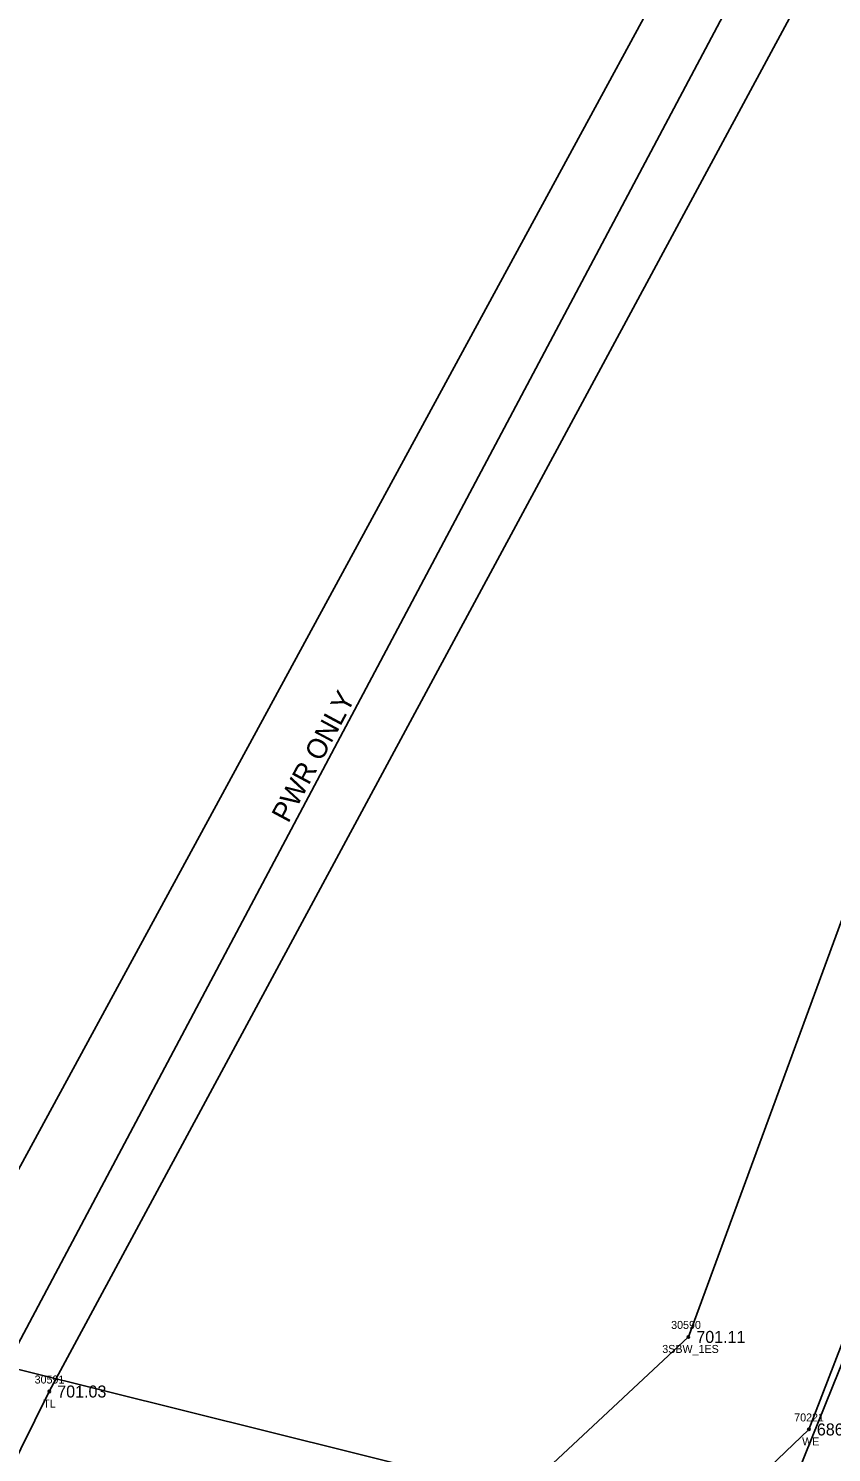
# Model space of a CAD drawing. Extents: x 1375131 to 1378678, y 999028 to 1004053.
# Drawn here: x 1377457.9 to 1377558.2, y 1001844.5 to 1002022.4 of the extents above; entities that cross this region are included whole.
import ezdxf

# ---------------------------------------------------------------- set-up
doc = ezdxf.new("R2010")
doc.units = 0
for name, color, linetype in [('RD_EX_DV_Prop', 7, 'Continuous'), ('RD_EX_Fence_Other', 7, 'Continuous'), ('RD_EX_Fence_Other_txCode', 7, 'Continuous'), ('RD_EX_H2O', 7, 'Continuous'), ('RD_EX_H2O_txCode', 7, 'Continuous'), ('RD_EX_SU_Elec', 7, 'Continuous'), ('RD_EX_TX_Fence_Other_ELEV', 7, 'Continuous'), ('RD_EX_TX_H2O_ELEV', 7, 'Continuous'), ('RD_EX_TX_VEG_ELEV', 7, 'Continuous'), ('RD_EX_VEG', 7, 'Continuous'), ('RD_EX_VEG_txCode', 7, 'Continuous'), ('RD_SMD_Locator', 7, 'Continuous'), ('RD_TX_Utilities', 7, 'Continuous')]:
    doc.layers.add(name, color=color, linetype=linetype)

msp = doc.modelspace()

# ---------------------------------------------------------------- linework, layer by layer
at = {"layer": 'RD_EX_DV_Prop'}
for points in [[(1377549.86, 1001831.61), (1377611.45, 1001984.12), (1377670.59, 1002066), (1377702.9, 1002207.93), (1377884.59, 1002382.26), (1377952.03, 1002369.22), (1378007.15, 1002415.65), (1377966.32, 1002503.97)], [(1377239.22, 1001933.68), (1377316.8, 1001925.5), (1377415.78, 1001865), (1377549.86, 1001831.61)]]:
    msp.add_lwpolyline(points, dxfattribs=at)
at = {"layer": 'RD_EX_Fence_Other'}
msp.add_lwpolyline([(1377637.49, 1002082.79), (1377602.37, 1002057.58), (1377580.56, 1002027.27), (1377564.26, 1001923.93), (1377540.33, 1001858.9), (1377456.19, 1001780.35), (1377421.26, 1001757.98), (1377378.17, 1001733.06)], dxfattribs=at)
at = {"layer": 'RD_EX_H2O'}
msp.add_lwpolyline([(1377375.48, 1001712.38), (1377425.1, 1001742.05), (1377478.82, 1001780.63), (1377516.49, 1001810.1), (1377555.39, 1001847.34), (1377570.71, 1001887.01), (1377585.15, 1001942.13), (1377603.16, 1001999.03), (1377641.82, 1002043.69), (1377653.81, 1002063.49)], dxfattribs=at)
at = {"layer": 'RD_EX_SU_Elec'}
msp.add_lwpolyline([(1377174.65, 1001934.87), (1377247.04, 1001903.65), (1377437.44, 1001822.1), (1377567.31, 1002066.68)], dxfattribs=at)
at = {"layer": 'RD_EX_VEG'}
for points in [[(1377636.58, 1002090.08), (1377595.82, 1002067.58), (1377573.9, 1002031.25), (1377561.3, 1002039.21), (1377460.46, 1001852.08), (1377433.84, 1001798.31), (1377321.3, 1001854.67)], [(1377534.01, 1002073.13), (1377547.87, 1002047.96), (1377449.99, 1001867.71), (1377414.83, 1001847.8), (1377322.94, 1001881.51), (1377257.82, 1001917.47), (1377246.23, 1001920.57)]]:
    msp.add_lwpolyline(points, dxfattribs=at)
at = {"layer": 'RD_SMD_Locator'}
for centre in [(1377540.33, 1001858.9), (1377460.46, 1001852.08), (1377555.39, 1001847.34)]:
    msp.add_circle(centre, 0.15, dxfattribs=at)

# ---------------------------------------------------------------- texts
at = {"layer": 'RD_EX_Fence_Other_txCode'}
for s, p in [('30590', (1377538.18, 1001859.9)), ('3SBW_1ES', (1377537.07, 1001856.9))]:
    msp.add_text(s, height=1, dxfattribs=at).set_placement(p)
at = {"layer": 'RD_EX_H2O_txCode'}
for s, p in [('70221', (1377553.56, 1001848.34)), ('WE', (1377554.55, 1001845.34))]:
    msp.add_text(s, height=1, dxfattribs=at).set_placement(p)
at = {"layer": 'RD_EX_TX_Fence_Other_ELEV'}
msp.add_text('701.11', height=1.5, dxfattribs=at).set_placement((1377541.33, 1001858.15))
at = {"layer": 'RD_EX_TX_H2O_ELEV'}
msp.add_text('686.93', height=1.5, dxfattribs=at).set_placement((1377556.39, 1001846.59))
at = {"layer": 'RD_EX_TX_VEG_ELEV'}
msp.add_text('701.03', height=1.5, dxfattribs=at).set_placement((1377461.46, 1001851.33))
at = {"layer": 'RD_EX_VEG_txCode'}
for s, p in [('30591', (1377458.63, 1001853.08)), ('TL', (1377459.69, 1001850.08))]:
    msp.add_text(s, height=1, dxfattribs=at).set_placement(p)
at = {"layer": 'RD_TX_Utilities'}
msp.add_text('PWR ONLY', height=2.5, rotation=61.7935, dxfattribs=at).set_placement((1377490.33, 1001923.01))

doc.saveas('drawing.dxf')
